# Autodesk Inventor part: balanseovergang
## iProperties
Created: 2010-02
Part Number: balanseovergang
Document SubType Name: Modeling
Designer: a31883
Density: 1 g/cm^3
Author: a31883
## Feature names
1. Extrusion1
2. Extrusion2
3. Hole1
4. Circular Pattern1
5. Extrusion3
